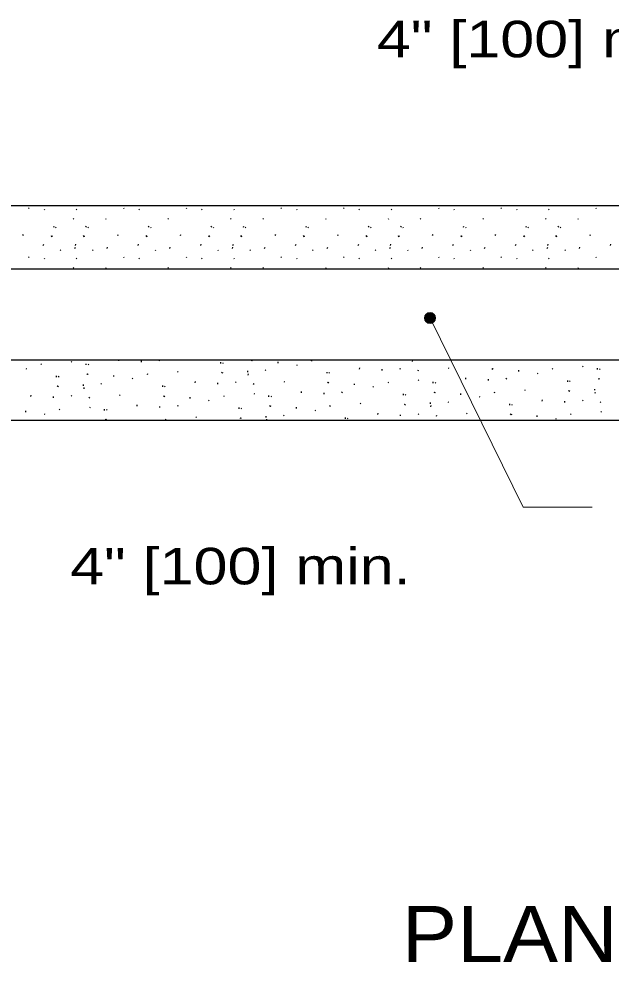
# Model space of a CAD drawing. Extents: x 1083.1 to 1117.1, y 697.4 to 741.4.
# Drawn here: x 1092.982 to 1095.513, y 709.842 to 713.873 of the extents above; entities that cross this region are included whole.
import ezdxf
from ezdxf.enums import TextEntityAlignment as Align

# ---------------------------------------------------------------- set-up
doc = ezdxf.new("R2010")
doc.units = 0
doc.header["$LTSCALE"] = 0.062
doc.layers.add('1', color=7, linetype='Continuous', lineweight=13)

msp = doc.modelspace()

# ---------------------------------------------------------------- hatches: boundary and pattern name
at = {"layer": '1'}
msp.add_hatch(color=256, dxfattribs=at).paths.add_polyline_path([(1094.76278, 712.59472, 1), (1094.71558, 712.59472, 1)])

# ---------------------------------------------------------------- linework, layer by layer
at = {"layer": '1', "lineweight": 25}
for p, q in [((1093.0235, 713.06617), (1093.02575, 713.06283)), ((1093.42875, 713.06617), (1093.43092, 713.06283)), ((1093.69642, 713.06617), (1093.69867, 713.06283)), ((1094.10167, 713.06617), (1094.10383, 713.06283)), ((1094.36933, 713.06617), (1094.37158, 713.06283)), ((1094.77458, 713.06617), (1094.77675, 713.06283)), ((1095.04225, 713.06617), (1095.0445, 713.06283)), ((1095.4475, 713.06617), (1095.44967, 713.06283)), ((1093.0895, 713.06008), (1093.09183, 713.05683)), ((1093.227, 713.06008), (1093.22933, 713.05683)), ((1093.49475, 713.06008), (1093.497, 713.05683)), ((1093.76242, 713.06008), (1093.76475, 713.05683)), ((1093.89992, 713.06008), (1093.90225, 713.05683)), ((1094.16767, 713.06008), (1094.16992, 713.05683)), ((1094.43533, 713.06008), (1094.43767, 713.05683)), ((1094.57283, 713.06008), (1094.57517, 713.05683)), ((1094.84058, 713.06008), (1094.84283, 713.05683)), ((1095.10825, 713.06008), (1095.11058, 713.05683)), ((1095.24575, 713.06008), (1095.24808, 713.05683)), ((1093.13083, 712.98292), (1093.133, 712.988)), ((1093.13892, 712.98292), (1093.14125, 712.97967)), ((1093.21392, 713.0205), (1093.21617, 713.01708)), ((1093.26833, 712.98292), (1093.2705, 712.988)), ((1093.27642, 712.98292), (1093.27875, 712.97967)), ((1093.35142, 713.0205), (1093.35367, 713.01708)), ((1093.536, 712.98292), (1093.53825, 712.988)), ((1093.54417, 712.98292), (1093.54642, 712.97967)), ((1093.61908, 713.0205), (1093.62142, 713.01708)), ((1093.80375, 712.98292), (1093.80592, 712.988)), ((1093.81183, 712.98292), (1093.81417, 712.97967)), ((1093.88683, 713.0205), (1093.88908, 713.01708)), ((1093.94125, 712.98292), (1093.94342, 712.988)), ((1093.94933, 712.98292), (1093.95167, 712.97967)), ((1094.02433, 713.0205), (1094.02658, 713.01708)), ((1094.20892, 712.98292), (1094.21117, 712.988)), ((1094.21708, 712.98292), (1094.21933, 712.97967)), ((1094.292, 713.0205), (1094.29433, 713.01708)), ((1094.47667, 712.98292), (1094.47883, 712.988)), ((1094.48475, 712.98292), (1094.487, 712.97967)), ((1094.55975, 713.0205), (1094.562, 713.01708)), ((1094.61417, 712.98292), (1094.61633, 712.988)), ((1094.62225, 712.98292), (1094.62458, 712.97967)), ((1094.69725, 713.0205), (1094.6995, 713.01708)), ((1094.88183, 712.98292), (1094.88408, 712.988)), ((1094.89, 712.98292), (1094.89225, 712.97967)), ((1094.96492, 713.0205), (1094.96725, 713.01708)), ((1095.14958, 712.98292), (1095.15175, 712.988)), ((1095.15767, 712.98292), (1095.15992, 712.97967)), ((1095.23267, 713.0205), (1095.23492, 713.01708)), ((1095.28708, 712.98292), (1095.28925, 712.988)), ((1095.29517, 712.98292), (1095.2975, 712.97967)), ((1095.37017, 713.0205), (1095.37242, 713.01708)), ((1092.99892, 712.947), (1093.00117, 712.952)), ((1093.11908, 712.947), (1093.12133, 712.94358)), ((1093.12133, 712.94575), (1093.1235, 712.94233)), ((1093.25658, 712.947), (1093.25883, 712.94358)), ((1093.25883, 712.94575), (1093.261, 712.94233)), ((1093.40408, 712.947), (1093.40642, 712.952)), ((1093.52433, 712.947), (1093.5265, 712.94358)), ((1093.5265, 712.94575), (1093.52875, 712.94233)), ((1093.67183, 712.947), (1093.67408, 712.952)), ((1093.792, 712.947), (1093.79425, 712.94358)), ((1093.79425, 712.94575), (1093.79642, 712.94233)), ((1093.9295, 712.947), (1093.93175, 712.94358)), ((1093.93175, 712.94575), (1093.93392, 712.94233)), ((1094.077, 712.947), (1094.07933, 712.952)), ((1094.19725, 712.947), (1094.19942, 712.94358)), ((1094.19942, 712.94575), (1094.20167, 712.94233)), ((1094.34475, 712.947), (1094.347, 712.952)), ((1094.46492, 712.947), (1094.46717, 712.94358)), ((1094.46717, 712.94575), (1094.46933, 712.94233)), ((1094.60242, 712.947), (1094.60467, 712.94358)), ((1094.60467, 712.94575), (1094.60683, 712.94233)), ((1094.74992, 712.947), (1094.75225, 712.952)), ((1094.87017, 712.947), (1094.87233, 712.94358)), ((1094.87233, 712.94575), (1094.87458, 712.94233)), ((1095.01767, 712.947), (1095.01992, 712.952)), ((1095.13783, 712.947), (1095.14008, 712.94358)), ((1095.14008, 712.94575), (1095.14225, 712.94233)), ((1095.27533, 712.947), (1095.27758, 712.94358)), ((1095.27758, 712.94575), (1095.27975, 712.94233)), ((1095.42283, 712.947), (1095.42517, 712.952)), ((1093.08608, 712.9055), (1093.08833, 712.91058)), ((1093.22358, 712.9055), (1093.22583, 712.91058)), ((1093.49125, 712.9055), (1093.49358, 712.91058)), ((1093.759, 712.9055), (1093.76125, 712.91058)), ((1093.8965, 712.9055), (1093.89875, 712.91058)), ((1094.16417, 712.9055), (1094.1665, 712.91058)), ((1094.43192, 712.9055), (1094.43417, 712.91058)), ((1094.56942, 712.9055), (1094.57167, 712.91058)), ((1094.83708, 712.9055), (1094.83942, 712.91058)), ((1095.10483, 712.9055), (1095.10708, 712.91058)), ((1095.24233, 712.9055), (1095.24458, 712.91058)), ((1095.51, 712.9055), (1095.51233, 712.91058)), ((1093.15883, 712.88617), (1093.161, 712.88283)), ((1093.22133, 712.89267), (1093.22358, 712.89775)), ((1093.29633, 712.88617), (1093.29858, 712.88283)), ((1093.35883, 712.89267), (1093.36108, 712.89775)), ((1093.56408, 712.88617), (1093.56625, 712.88283)), ((1093.62658, 712.89267), (1093.62875, 712.89775)), ((1093.83175, 712.88617), (1093.83392, 712.88283)), ((1093.89425, 712.89267), (1093.8965, 712.89775)), ((1093.96925, 712.88617), (1093.9715, 712.88283)), ((1094.03183, 712.89267), (1094.034, 712.89775)), ((1094.237, 712.88617), (1094.23917, 712.88283)), ((1094.2995, 712.89267), (1094.30167, 712.89775)), ((1094.50467, 712.88617), (1094.50683, 712.88283)), ((1094.56717, 712.89267), (1094.56942, 712.89775)), ((1094.64217, 712.88617), (1094.64433, 712.88283)), ((1094.70475, 712.89267), (1094.70692, 712.89775)), ((1094.90983, 712.88617), (1094.91208, 712.88283)), ((1094.97242, 712.89267), (1094.97458, 712.89775)), ((1095.17758, 712.88617), (1095.17975, 712.88283)), ((1095.24008, 712.89267), (1095.24233, 712.89775)), ((1095.31508, 712.88617), (1095.31725, 712.88283)), ((1095.37767, 712.89267), (1095.37983, 712.89775)), ((1093.0235, 712.85692), (1093.02575, 712.85358)), ((1093.0895, 712.85083), (1093.09183, 712.84758)), ((1093.227, 712.85083), (1093.22933, 712.84758)), ((1093.42875, 712.85692), (1093.43092, 712.85358)), ((1093.49475, 712.85083), (1093.497, 712.84758)), ((1093.69642, 712.85692), (1093.69867, 712.85358)), ((1093.76242, 712.85083), (1093.76475, 712.84758)), ((1093.89992, 712.85083), (1093.90225, 712.84758)), ((1094.10167, 712.85692), (1094.10383, 712.85358)), ((1094.16767, 712.85083), (1094.16992, 712.84758)), ((1094.36933, 712.85692), (1094.37158, 712.85358)), ((1094.43533, 712.85083), (1094.43767, 712.84758)), ((1094.57283, 712.85083), (1094.57517, 712.84758)), ((1094.77458, 712.85692), (1094.77675, 712.85358)), ((1094.84058, 712.85083), (1094.84283, 712.84758)), ((1095.04225, 712.85692), (1095.0445, 712.85358)), ((1095.10825, 712.85083), (1095.11058, 712.84758)), ((1095.24575, 712.85083), (1095.24808, 712.84758)), ((1095.4475, 712.85692), (1095.44967, 712.85358)), ((1093.21392, 712.81117), (1093.21617, 712.80783)), ((1093.35142, 712.81117), (1093.35367, 712.80783)), ((1093.61908, 712.81117), (1093.62142, 712.80783)), ((1093.88683, 712.81117), (1093.88908, 712.80783)), ((1094.02433, 712.81117), (1094.02658, 712.80783)), ((1094.292, 712.81117), (1094.29433, 712.80783)), ((1094.55975, 712.81117), (1094.562, 712.80783)), ((1094.69725, 712.81117), (1094.6995, 712.80783)), ((1094.96492, 712.81117), (1094.96725, 712.80783)), ((1095.23267, 712.81117), (1095.23492, 712.80783)), ((1095.37017, 712.81117), (1095.37242, 712.80783)), ((1090.79808, 712.41658), (1097.47717, 712.41658)), ((1093.01167, 712.37975), (1093.015, 712.3775)), ((1093.07517, 712.39883), (1093.0785, 712.39667)), ((1093.20533, 712.40867), (1093.20875, 712.40642)), ((1093.26983, 712.39425), (1093.27, 712.39975)), ((1093.27742, 712.39733), (1093.28075, 712.39508)), ((1093.40925, 712.41183), (1093.40942, 712.41658)), ((1093.50558, 712.406), (1093.50583, 712.41158)), ((1093.58025, 712.41533), (1093.58358, 712.413)), ((1093.84467, 712.40083), (1093.84483, 712.40633)), ((1093.85217, 712.40383), (1093.8555, 712.40167)), ((1093.97475, 712.41458), (1093.97808, 712.41233)), ((1093.97725, 712.41425), (1093.98058, 712.412)), ((1094.08992, 712.40258), (1094.09008, 712.40808)), ((1094.16808, 712.39558), (1094.17142, 712.39333)), ((1094.23158, 712.41467), (1094.23492, 712.4125)), ((1094.43817, 712.37617), (1094.43833, 712.38167)), ((1094.60917, 712.37967), (1094.6125, 712.37733)), ((1094.66475, 712.40917), (1094.66492, 712.41467)), ((1094.81583, 712.38233), (1094.81925, 712.38)), ((1095.00367, 712.37892), (1095.007, 712.37667)), ((1095.00617, 712.37858), (1095.0095, 712.37633)), ((1095.2605, 712.379), (1095.26383, 712.37683)), ((1095.39067, 712.38883), (1095.394, 712.38658)), ((1095.45517, 712.37442), (1095.45533, 712.37992)), ((1093.14242, 712.34275), (1093.1425, 712.34825)), ((1093.14992, 712.34583), (1093.15325, 712.34358)), ((1093.2725, 712.35658), (1093.27575, 712.35425)), ((1093.275, 712.35625), (1093.27825, 712.35392)), ((1093.38758, 712.3445), (1093.38775, 712.35)), ((1093.52925, 712.35667), (1093.53258, 712.35442)), ((1093.65942, 712.36642), (1093.66283, 712.36417)), ((1093.84725, 712.36308), (1093.85058, 712.36075)), ((1093.84975, 712.36275), (1093.85308, 712.36042)), ((1093.95967, 712.36383), (1093.95992, 712.36933)), ((1093.96242, 712.35108), (1093.96258, 712.35658)), ((1094.03442, 712.37308), (1094.03767, 712.37083)), ((1094.29875, 712.35858), (1094.29892, 712.36408)), ((1094.30625, 712.36167), (1094.30967, 712.35942)), ((1094.5345, 712.37033), (1094.53467, 712.37583)), ((1094.68567, 712.3725), (1094.689, 712.37025)), ((1094.89225, 712.33392), (1094.89242, 712.33942)), ((1095.11883, 712.36692), (1095.119, 712.37242)), ((1095.197, 712.35992), (1095.20025, 712.35767)), ((1095.46267, 712.3775), (1095.466, 712.37525)), ((1093.145, 712.305), (1093.14825, 712.30275)), ((1093.1475, 712.30467), (1093.15083, 712.30242)), ((1093.25733, 712.30575), (1093.25758, 712.31125)), ((1093.26017, 712.293), (1093.26025, 712.2985)), ((1093.33208, 712.31508), (1093.33542, 712.31275)), ((1093.46583, 712.3375), (1093.46908, 712.33525)), ((1093.5965, 712.30058), (1093.59667, 712.306)), ((1093.604, 712.30358), (1093.60733, 712.30133)), ((1093.73583, 712.31808), (1093.73608, 712.32358)), ((1093.83217, 712.31225), (1093.83242, 712.31783)), ((1093.90692, 712.32158), (1093.91017, 712.31933)), ((1093.98333, 712.31442), (1093.98675, 712.31217)), ((1094.1135, 712.32425), (1094.11692, 712.32192)), ((1094.30133, 712.32092), (1094.30467, 712.31858)), ((1094.30392, 712.3205), (1094.30717, 712.31825)), ((1094.4165, 712.30883), (1094.41667, 712.31433)), ((1094.49467, 712.30183), (1094.498, 712.29958)), ((1094.55817, 712.32092), (1094.5615, 712.31875)), ((1094.68833, 712.33075), (1094.69175, 712.3285)), ((1094.75283, 712.31642), (1094.753, 712.32183)), ((1094.76033, 712.31942), (1094.76375, 712.31717)), ((1094.98858, 712.32817), (1094.98883, 712.33367)), ((1095.06325, 712.33742), (1095.06658, 712.33517)), ((1095.32767, 712.32292), (1095.32783, 712.32842)), ((1095.33517, 712.326), (1095.3385, 712.32375)), ((1095.45775, 712.33675), (1095.46108, 712.33442)), ((1095.46025, 712.33642), (1095.46358, 712.33408)), ((1093.0335, 712.26), (1093.03375, 712.2655)), ((1093.12983, 712.25425), (1093.13008, 712.25975)), ((1093.20458, 712.2635), (1093.20792, 712.26125)), ((1093.41125, 712.26617), (1093.41458, 712.26392)), ((1093.59908, 712.26283), (1093.60242, 712.2605)), ((1093.60158, 712.2625), (1093.60492, 712.26017)), ((1093.85583, 712.26292), (1093.85925, 712.26067)), ((1093.986, 712.27275), (1093.98942, 712.27042)), ((1094.05058, 712.25833), (1094.05075, 712.26383)), ((1094.05808, 712.26133), (1094.06142, 712.25917)), ((1094.18992, 712.27583), (1094.19017, 712.28142)), ((1094.28625, 712.27008), (1094.2865, 712.27558)), ((1094.361, 712.27942), (1094.36425, 712.27708)), ((1094.62533, 712.26483), (1094.6255, 712.27033)), ((1094.63292, 712.26792), (1094.63625, 712.26567)), ((1094.7555, 712.27867), (1094.75875, 712.27633)), ((1094.758, 712.27833), (1094.76125, 712.276)), ((1094.87058, 712.26667), (1094.87075, 712.27217)), ((1094.94883, 712.25958), (1094.95208, 712.25742)), ((1095.01225, 712.27875), (1095.01558, 712.2765)), ((1095.14242, 712.28858), (1095.14583, 712.28625)), ((1095.33025, 712.28525), (1095.33358, 712.28292)), ((1095.33275, 712.28483), (1095.33608, 712.28258)), ((1095.44267, 712.28592), (1095.44292, 712.29142)), ((1095.44542, 712.27317), (1095.44558, 712.27867)), ((1093.28108, 712.25633), (1093.28442, 712.25417)), ((1093.48758, 712.21775), (1093.48783, 712.22333)), ((1093.584, 712.212), (1093.58417, 712.2175)), ((1093.65867, 712.22133), (1093.662, 712.219)), ((1093.71425, 712.25083), (1093.71433, 712.25633)), ((1093.79242, 712.24375), (1093.79567, 712.24158)), ((1094.05317, 712.22058), (1094.0565, 712.21825)), ((1094.05567, 712.22025), (1094.059, 712.21792)), ((1094.30992, 712.22067), (1094.31333, 712.2185)), ((1094.44017, 712.2305), (1094.4435, 712.22825)), ((1094.628, 712.22717), (1094.63125, 712.22483)), ((1094.6305, 712.22683), (1094.63375, 712.2245)), ((1094.74033, 712.22783), (1094.74058, 712.23333)), ((1094.74308, 712.21517), (1094.74325, 712.22058)), ((1094.81508, 712.23717), (1094.81842, 712.23483)), ((1095.0795, 712.22267), (1095.07958, 712.22817)), ((1095.087, 712.22567), (1095.09033, 712.2235)), ((1095.21883, 712.24017), (1095.21908, 712.24575)), ((1095.31517, 712.23442), (1095.31542, 712.23992)), ((1095.38992, 712.24375), (1095.39317, 712.24142)), ((1095.46633, 712.2365), (1095.46967, 712.23433)), ((1093.01192, 712.19275), (1093.01208, 712.19825)), ((1093.09008, 712.18575), (1093.09333, 712.1835)), ((1093.15358, 712.20483), (1093.15692, 712.20258)), ((1093.28375, 712.21467), (1093.28708, 712.21233)), ((1093.34825, 712.20025), (1093.34842, 712.20575)), ((1093.35575, 712.20333), (1093.35908, 712.20108)), ((1093.92308, 712.20683), (1093.92325, 712.21233)), ((1093.93058, 712.20983), (1093.93392, 712.20767)), ((1094.11275, 712.17908), (1094.11608, 712.17675)), ((1094.16833, 712.20858), (1094.1685, 712.21408)), ((1094.2465, 712.20158), (1094.24975, 712.19933)), ((1094.5165, 712.18208), (1094.51675, 712.18767)), ((1094.61283, 712.17633), (1094.61308, 712.18183)), ((1094.68758, 712.18567), (1094.69092, 712.18333)), ((1094.76408, 712.17842), (1094.76742, 712.17625)), ((1094.89425, 712.18825), (1094.89758, 712.186)), ((1095.08208, 712.18492), (1095.08533, 712.18258)), ((1095.08458, 712.18458), (1095.08792, 712.18225)), ((1095.19725, 712.17292), (1095.19733, 712.17842)), ((1095.33883, 712.185), (1095.34217, 712.18275)), ((1095.469, 712.19483), (1095.47242, 712.1925)), ((1097.47717, 712.15767), (1090.81242, 712.15767)), ((1093.35083, 712.1625), (1093.35417, 712.16025)), ((1093.35333, 712.16217), (1093.35667, 712.15992)), ((1093.60767, 712.16258), (1093.611, 712.16042)), ((1093.73783, 712.17242), (1093.74117, 712.17017)), ((1093.92567, 712.16908), (1093.929, 712.16675)), ((1093.92817, 712.16875), (1093.9315, 712.16642)), ((1094.03808, 712.16975), (1094.03825, 712.17533)), ((1094.04083, 712.15767), (1094.041, 712.16258)), ((1094.37717, 712.16458), (1094.37733, 712.17008)), ((1094.38467, 712.16758), (1094.388, 712.16542)), ((1095.27542, 712.16592), (1095.27867, 712.16367))]:
    msp.add_line(p, q, dxfattribs=at)
at = {"layer": '1'}
for p in [(1094.73917, 712.59475), (1095.43158, 711.78642)]:
    msp.add_line(p, (1095.137, 711.78642), dxfattribs=at)
at = {"layer": '1', "lineweight": 25}
msp.add_lwpolyline([(1097.47983, 713.07375), (1090.79808, 713.07375), (1090.79808, 712.80517), (1097.47983, 712.80517)], dxfattribs=at)
at = {"layer": '1'}
msp.add_circle((1094.73918, 712.59472), 0.0236, dxfattribs=at)

# ---------------------------------------------------------------- texts
for s, height, width, p in [('4" [100] min.', 0.156, 1.25, (1095.23929, 713.709)), ('4" [100] min.', 0.156, 1.25, (1093.92837, 711.45683)), ('PLAN', 0.24, 1.1, (1095.08017, 709.84242))]:
    msp.add_text(s, height=height, dxfattribs=dict(at, width=width)).set_placement(p, align=Align.CENTER)

doc.saveas('drawing.dxf')
